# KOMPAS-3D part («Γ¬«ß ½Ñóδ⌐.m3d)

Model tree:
1. Эскиз:1
2. Операция выдавливания:1
     Расстояние 1 = 0.5; Расстояние 2 = 1.1
3. Эскиз:2
4. Операция выдавливания:2
     Расстояние 1 = 2; Расстояние 2 = 1.1
5. Эскиз:3
6. Операция выдавливания:3
     Расстояние 1 = 2; Расстояние 2 = 1.1
7. Эскиз:4
8. Операция выдавливания:4
     Расстояние 1 = 8; Расстояние 2 = 1.1
9. Эскиз:5
10. Вырезать элемент выдавливания:1
     Расстояние 2 = 4; Расстояние 1 = 12.4454
11. Скругление:1
     Радиус = 0.5
12. Скругление:2
     Радиус = 0.5
13. Скругление:5
     Радиус = 0.5
14. Эскиз:7
15. Операция выдавливания:6
     Расстояние 1 = 0.5; Расстояние 2 = 1.1
16. Эскиз:9
17. Операция выдавливания:7
     Расстояние 1 = 0.3; Расстояние 2 = 1.1
18. Скругление:7
     Радиус = 0.5
19. Скругление:8
     Радиус = 0.5

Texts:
  Сплав АЛ8  ГОСТ 1583-93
